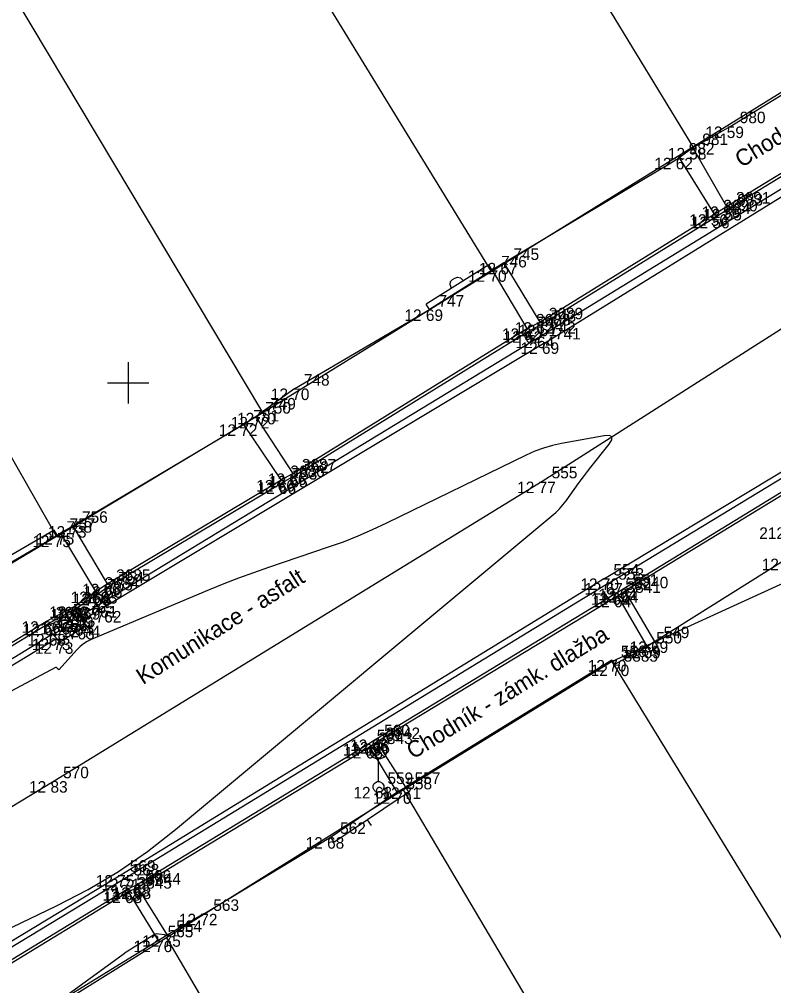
# Model space of a CAD drawing. Extents: x -703403 to -701924, y -1022520 to -1021856.
# Drawn here: x -703227.64 to -703209.32, y -1022139.64 to -1022116.18 of the extents above; entities that cross this region are included whole.
import ezdxf

# ---------------------------------------------------------------- set-up
doc = ezdxf.new("R2010")
doc.units = 0
for name, color, linetype in [('Ex_Minor Contours', 7, 'Continuous'), ('Z_bodove_pole_vysky', 7, 'Continuous'), ('Z_body', 7, 'Continuous'), ('Z_body_cisla', 7, 'Continuous'), ('Z_body_vysky_redukovane', 7, 'Continuous'), ('Z_budova', 7, 'Continuous'), ('Z_hektometricka_sit', 7, 'Continuous'), ('Z_katastr_hranice', 7, 'Continuous'), ('Z_katastr_vnitrni_kresba', 7, 'Continuous'), ('Z_komunikace', 7, 'Continuous'), ('Z_komunikace_osa', 7, 'Continuous'), ('Z_obruba', 7, 'Continuous'), ('Z_ploty', 7, 'Continuous'), ('Z_ploty_znacky', 7, 'Continuous'), ('Z_popisy', 7, 'Continuous'), ('Z_rozhranni', 7, 'Continuous'), ('Z_site_kanalizace_znaky', 7, 'Continuous'), ('Z_site_vo_znaky', 7, 'Continuous'), ('Z_vstupy', 7, 'Continuous'), ('Z_zlabek', 7, 'Continuous')]:
    doc.layers.add(name, color=color, linetype=linetype)

# ---------------------------------------------------------------- blocks, each defined once
blk = doc.blocks.new('POINT_DISPLAY')
blk.add_line((0, 0), (0, 0))
blk = doc.blocks.new('Z34')
for p, q in [((-0.2, 0.93), (-0.15, 1.02)), ((-0.15, 1.02), (-0.05, 1.07)), ((0.15, 0.72), (-0.15, 1.02)), ((0.15, 1.02), (-0.15, 0.72)), ((-0.05, 1.07), (0.05, 1.07)), ((0.05, 1.07), (0.15, 1.02)), ((0.15, 1.02), (0.2, 0.93)), ((-0.2, 0.82), (-0.2, 0.93)), ((-0.15, 0.72), (-0.2, 0.82)), ((-0.05, 0.68), (-0.15, 0.72)), ((0.15, 0.72), (0.05, 0.68)), ((0.2, 0.82), (0.15, 0.72)), ((0.2, 0.93), (0.2, 0.82)), ((0.05, 0.68), (-0.05, 0.68)), ((0, 0.13), (0, 0.68)), ((-0.13, 0.03), (-0.1, 0.08)), ((-0.13, -0.03), (-0.13, 0.03)), ((-0.1, 0.08), (-0.08, 0.1)), ((-0.08, 0.1), (-0.03, 0.13)), ((-0.03, 0.13), (0.03, 0.13)), ((0.03, 0.13), (0.08, 0.1)), ((0.08, 0.1), (0.1, 0.08)), ((0.1, 0.08), (0.13, 0.03)), ((0.13, 0.03), (0.13, -0.03)), ((-0.1, -0.08), (-0.13, -0.03)), ((-0.08, -0.1), (-0.1, -0.08)), ((-0.03, -0.13), (-0.08, -0.1)), ((0.03, -0.13), (-0.03, -0.13)), ((0.08, -0.1), (0.03, -0.13)), ((0.1, -0.08), (0.08, -0.1)), ((0.13, -0.03), (0.1, -0.08))]:
    blk.add_line(p, q)
blk = doc.blocks.new('Z46260')
for p, q in [((0.13, 0.13), (-0.13, 0.13)), ((-0.13, 0.13), (-0.13, -0.13)), ((0.13, 0), (-0.13, 0)), ((0.13, -0.13), (0.13, 0.13)), ((-0.13, -0.13), (0.13, -0.13))]:
    blk.add_line(p, q)
blk = doc.blocks.new('Z216')
for p, q in [((-0.17, 0), (-0.15, 0.1)), ((-0.15, 0.1), (-0.1, 0.15)), ((-0.1, 0.15), (-0.03, 0.17)), ((-0.03, 0.17), (0.03, 0.17)), ((0.03, 0.17), (0.1, 0.15)), ((0.1, 0.15), (0.15, 0.1)), ((0.15, 0.1), (0.17, 0))]:
    blk.add_line(p, q)
blk = doc.blocks.new('Z210')
blk.add_line((0, 0), (0, 0.17))

msp = doc.modelspace()

# ---------------------------------------------------------------- linework, layer by layer
at = {"layer": 'Ex_Minor Contours'}
for points in [[(-703231.075, -1022139.779), (-703226.738, -1022137.698), (-703225.974, -1022137.302), (-703225.237, -1022136.861), (-703224.53, -1022136.375), (-703223.851, -1022135.845), (-703214.703, -1022128.233), (-703214.609, -1022128.15), (-703214.52, -1022128.061), (-703214.438, -1022127.966), (-703214.361, -1022127.866), (-703214.065, -1022127.455), (-703213.991, -1022127.353), (-703213.915, -1022127.252), (-703213.838, -1022127.151), (-703213.76, -1022127.051), (-703213.316, -1022126.489), (-703213.248, -1022126.382), (-703213.245, -1022126.313), (-703213.307, -1022126.283), (-703213.434, -1022126.292), (-703214.469, -1022126.475), (-703214.692, -1022126.523), (-703214.91, -1022126.585), (-703215.123, -1022126.663), (-703215.332, -1022126.756), (-703218.722, -1022128.411), (-703219.069, -1022128.574), (-703219.421, -1022128.725), (-703219.778, -1022128.866), (-703220.139, -1022128.994), (-703221.593, -1022129.487), (-703221.955, -1022129.613), (-703222.315, -1022129.746), (-703222.673, -1022129.885), (-703223.028, -1022130.03), (-703225.895, -1022131.234), (-703225.993, -1022131.281), (-703226.084, -1022131.339), (-703226.168, -1022131.406), (-703226.245, -1022131.483), (-703226.673, -1022131.957), (-703226.68, -1022131.963), (-703226.688, -1022131.965), (-703226.695, -1022131.963), (-703226.702, -1022131.956), (-703226.73, -1022131.92), (-703226.737, -1022131.913), (-703226.746, -1022131.909), (-703226.754, -1022131.909), (-703226.764, -1022131.913), (-703230.733, -1022134.026)], [(-703226.72, -1022128.71), (-703226.64, -1022128.65)], [(-703224.05, -1022138.41), (-703224.316, -1022138.38), (-703224.32, -1022138.379), (-703224.324, -1022138.38), (-703224.327, -1022138.381), (-703224.331, -1022138.382), (-703224.348, -1022138.39), (-703224.354, -1022138.393), (-703224.358, -1022138.395), (-703224.817, -1022138.675), (-703224.894, -1022138.723), (-703224.97, -1022138.773), (-703225.045, -1022138.824), (-703225.119, -1022138.877), (-703226.755, -1022140.07)]]:
    msp.add_lwpolyline(points, dxfattribs=at)
at = {"layer": 'Z_budova'}
for p, q in [((-703211.28, -1022119.3), (-703211.61, -1022119.54)), ((-703215.87, -1022122.09), (-703211.61, -1022119.54)), ((-703216.16, -1022122.27), (-703216.24, -1022122.14)), ((-703215.87, -1022122.09), (-703216.16, -1022122.27)), ((-703221.9, -1022125.83), (-703222.19, -1022126.01)), ((-703221.77, -1022125.73), (-703221.9, -1022125.83)), ((-703222.19, -1022126.01), (-703226.34, -1022128.48)), ((-703226.34, -1022128.48), (-703226.64, -1022128.65)), ((-703226.72, -1022128.71), (-703226.8, -1022128.58)), ((-703226.64, -1022128.65), (-703226.72, -1022128.71)), ((-703213.25, -1022131.73), (-703218.26, -1022134.82)), ((-703213.25, -1022131.73), (-703213.18, -1022131.84)), ((-703218.26, -1022134.82), (-703218.18, -1022134.95)), ((-703224.26, -1022138.54), (-703229.25, -1022141.6)), ((-703224.05, -1022138.41), (-703224.26, -1022138.54))]:
    msp.add_line(p, q, dxfattribs=at)
at = {"layer": 'Z_hektometricka_sit'}
for p, q in [((-703225, -1022124.5), (-703225, -1022125.5)), ((-703225.5, -1022125), (-703224.5, -1022125))]:
    msp.add_line(p, q, dxfattribs=at)
at = {"layer": 'Z_katastr_hranice'}
for p, q in [((-703224.86, -1022108.15), (-703216.18, -1022122.3)), ((-703235.18, -1022113.95), (-703226.74, -1022128.73)), ((-703211.28, -1022119.27), (-703205.53, -1022115.72)), ((-703216.18, -1022122.3), (-703211.28, -1022119.27)), ((-703221.73, -1022125.72), (-703216.18, -1022122.3)), ((-703226.74, -1022128.73), (-703221.73, -1022125.72)), ((-703205.55, -1022128.24), (-703213.24, -1022131.77)), ((-703226.74, -1022128.73), (-703232.45, -1022132.14)), ((-703213.24, -1022131.77), (-703218.31, -1022134.88)), ((-703218.31, -1022134.88), (-703224.07, -1022138.47)), ((-703196.15, -1022172.3), (-703218.31, -1022134.88)), ((-703224.07, -1022138.47), (-703229.34, -1022141.75))]:
    msp.add_line(p, q, dxfattribs=at)
at = {"layer": 'Z_katastr_vnitrni_kresba'}
for p, q in [((-703221.49, -1022102.56), (-703211.28, -1022119.27)), ((-703221.73, -1022125.72), (-703231.79, -1022108.89)), ((-703190.45, -1022168.92), (-703213.24, -1022131.77)), ((-703224.07, -1022138.47), (-703208.36, -1022165.17))]:
    msp.add_line(p, q, dxfattribs=at)
at = {"layer": 'Z_komunikace'}
for p, q in [((-703214.86, -1022124.02), (-703204.83, -1022117.83)), ((-703214.86, -1022124.02), (-703226.12, -1022130.77)), ((-703213.43, -1022129.75), (-703207.78, -1022126.35)), ((-703213.43, -1022129.75), (-703225.18, -1022136.95)), ((-703226.12, -1022130.77), (-703226.01, -1022130.9)), ((-703226.01, -1022130.9), (-703226.66, -1022131.3)), ((-703226.73, -1022131.21), (-703231.61, -1022134.15)), ((-703226.66, -1022131.3), (-703226.73, -1022131.21)), ((-703225.18, -1022136.95), (-703231.78, -1022140.94))]:
    msp.add_line(p, q, dxfattribs=at)
at = {"layer": 'Z_komunikace_osa'}
for p, q in [((-703203.08, -1022119.83), (-703214.94, -1022127.4)), ((-703214.94, -1022127.4), (-703226.8, -1022134.67)), ((-703226.8, -1022134.67), (-703237.77, -1022141.31))]:
    msp.add_line(p, q, dxfattribs=at)
at = {"layer": 'Z_obruba'}
for p, q in [((-703210.46, -1022120.72), (-703205.08, -1022117.43)), ((-703204.92, -1022117.72), (-703214.98, -1022123.88)), ((-703210.76, -1022120.91), (-703210.46, -1022120.72)), ((-703215, -1022123.53), (-703210.76, -1022120.91)), ((-703215.31, -1022123.68), (-703215, -1022123.53)), ((-703221, -1022127.2), (-703215.31, -1022123.68)), ((-703214.98, -1022123.88), (-703226.17, -1022130.67)), ((-703213.31, -1022129.86), (-703207.72, -1022126.46)), ((-703207.53, -1022126.76), (-703212.93, -1022130.06)), ((-703221.28, -1022127.36), (-703221, -1022127.2)), ((-703225.51, -1022129.88), (-703221.28, -1022127.36)), ((-703225.79, -1022130.07), (-703225.51, -1022129.88)), ((-703213.31, -1022129.86), (-703225.09, -1022137.04)), ((-703226.31, -1022130.43), (-703225.79, -1022130.07)), ((-703213.11, -1022130.17), (-703212.93, -1022130.06)), ((-703218.97, -1022133.72), (-703213.11, -1022130.17)), ((-703226.98, -1022130.79), (-703226.31, -1022130.43)), ((-703231.74, -1022133.67), (-703226.98, -1022130.79)), ((-703226.84, -1022131.1), (-703231.66, -1022134.04)), ((-703224.77, -1022137.25), (-703219.14, -1022133.84)), ((-703219.14, -1022133.84), (-703218.97, -1022133.72)), ((-703225.09, -1022137.04), (-703231.7, -1022141.05)), ((-703229.96, -1022140.38), (-703224.99, -1022137.35)), ((-703224.99, -1022137.35), (-703224.77, -1022137.25))]:
    msp.add_line(p, q, dxfattribs=at)
at = {"layer": 'Z_ploty'}
for p, q in [((-703216.24, -1022122.14), (-703217.76, -1022123.09)), ((-703216.16, -1022122.27), (-703217.68, -1022123.22)), ((-703217.68, -1022123.22), (-703217.76, -1022123.09)), ((-703226.8, -1022128.58), (-703228.67, -1022129.67)), ((-703226.72, -1022128.71), (-703228.59, -1022129.8)), ((-703212.21, -1022131.28), (-703212.39, -1022131.41)), ((-703212.21, -1022131.28), (-703212.13, -1022131.41)), ((-703212.39, -1022131.41), (-703212.31, -1022131.53)), ((-703212.13, -1022131.41), (-703212.31, -1022131.53)), ((-703218.47, -1022134.94), (-703218.26, -1022134.82)), ((-703220.08, -1022136.03), (-703218.47, -1022134.94)), ((-703220, -1022136.15), (-703218.39, -1022135.07)), ((-703218.39, -1022135.07), (-703218.18, -1022134.95)), ((-703220.08, -1022136.03), (-703220, -1022136.15))]:
    msp.add_line(p, q, dxfattribs=at)
at = {"layer": 'Z_rozhranni'}
for p, q in [((-703226.17, -1022130.67), (-703226.28, -1022130.49)), ((-703226.84, -1022131.1), (-703226.95, -1022130.85)), ((-703226.17, -1022130.67), (-703226.12, -1022130.77)), ((-703226.84, -1022131.1), (-703226.73, -1022131.21))]:
    msp.add_line(p, q, dxfattribs=at)
at = {"layer": 'Z_vstupy'}
for p, q in [((-703210.37, -1022118.78), (-703207.13, -1022116.78)), ((-703211.28, -1022119.3), (-703210.37, -1022118.78)), ((-703220.95, -1022125.14), (-703217.68, -1022123.22)), ((-703220.95, -1022125.14), (-703221.77, -1022125.73)), ((-703212.21, -1022131.28), (-703209, -1022129.27)), ((-703212.39, -1022131.41), (-703213.18, -1022131.84)), ((-703223.16, -1022137.89), (-703220.08, -1022136.03)), ((-703223.16, -1022137.89), (-703224.05, -1022138.41))]:
    msp.add_line(p, q, dxfattribs=at)
at = {"layer": 'Z_zlabek'}
for p, q in [((-703210.42, -1022120.78), (-703205.05, -1022117.49)), ((-703211.28, -1022119.3), (-703210.46, -1022120.72)), ((-703211.61, -1022119.54), (-703210.76, -1022120.91)), ((-703210.72, -1022120.97), (-703210.42, -1022120.78)), ((-703214.96, -1022123.59), (-703210.72, -1022120.97)), ((-703215.87, -1022122.09), (-703215, -1022123.53)), ((-703216.16, -1022122.27), (-703215.31, -1022123.68)), ((-703215.27, -1022123.75), (-703214.96, -1022123.59)), ((-703220.97, -1022127.26), (-703215.27, -1022123.75)), ((-703221.9, -1022125.83), (-703221, -1022127.2)), ((-703221.28, -1022127.36), (-703222.19, -1022126.01)), ((-703212.97, -1022130), (-703207.57, -1022126.7)), ((-703221.25, -1022127.42), (-703220.97, -1022127.26)), ((-703225.47, -1022129.94), (-703221.25, -1022127.42)), ((-703226.34, -1022128.48), (-703225.51, -1022129.88)), ((-703226.64, -1022128.65), (-703225.79, -1022130.07)), ((-703226.28, -1022130.49), (-703225.74, -1022130.12)), ((-703225.74, -1022130.12), (-703225.47, -1022129.94)), ((-703219, -1022133.66), (-703213.15, -1022130.11)), ((-703213.15, -1022130.11), (-703212.97, -1022130)), ((-703212.93, -1022130.06), (-703212.21, -1022131.28)), ((-703213.11, -1022130.17), (-703212.39, -1022131.41)), ((-703226.95, -1022130.85), (-703226.28, -1022130.49)), ((-703231.7, -1022133.73), (-703226.95, -1022130.85)), ((-703219.18, -1022133.77), (-703219, -1022133.66)), ((-703224.8, -1022137.19), (-703219.18, -1022133.77)), ((-703219.14, -1022133.84), (-703218.47, -1022134.94)), ((-703218.97, -1022133.72), (-703218.26, -1022134.82)), ((-703225.02, -1022137.29), (-703224.8, -1022137.19)), ((-703230, -1022140.32), (-703225.02, -1022137.29)), ((-703224.26, -1022138.54), (-703224.99, -1022137.35)), ((-703224.77, -1022137.25), (-703224.05, -1022138.41))]:
    msp.add_line(p, q, dxfattribs=at)

# ---------------------------------------------------------------- block references
at = {"layer": 'Z_body'}
for p in [(-703210.37, -1022118.78), (-703211.28, -1022119.3), (-703211.61, -1022119.54), (-703210.46, -1022120.72), (-703210.42, -1022120.78), (-703210.76, -1022120.91), (-703210.72, -1022120.97), (-703215.87, -1022122.09), (-703216.16, -1022122.27), (-703217.68, -1022123.22), (-703215, -1022123.53), (-703214.96, -1022123.59), (-703215.31, -1022123.68), (-703215.27, -1022123.75), (-703214.98, -1022123.88), (-703214.86, -1022124.02), (-703220.95, -1022125.14), (-703221.9, -1022125.83), (-703221.77, -1022125.73), (-703222.19, -1022126.01), (-703221, -1022127.2), (-703220.97, -1022127.26), (-703221.28, -1022127.36), (-703221.25, -1022127.42), (-703214.94, -1022127.4), (-703226.34, -1022128.48), (-703226.72, -1022128.71), (-703226.64, -1022128.65), (-703225.51, -1022129.88), (-703213.43, -1022129.75), (-703213.31, -1022129.86), (-703225.79, -1022130.07), (-703225.74, -1022130.12), (-703225.47, -1022129.94), (-703213.15, -1022130.11), (-703212.97, -1022130), (-703212.93, -1022130.06), (-703213.11, -1022130.17), (-703226.31, -1022130.43), (-703226.28, -1022130.49), (-703226.98, -1022130.79), (-703226.95, -1022130.85), (-703226.53, -1022130.83), (-703226.17, -1022130.67), (-703226.12, -1022130.77), (-703226.84, -1022131.1), (-703226.01, -1022130.9), (-703226.73, -1022131.21), (-703226.66, -1022131.3), (-703212.21, -1022131.28), (-703212.39, -1022131.41), (-703213.25, -1022131.73), (-703213.18, -1022131.84), (-703219, -1022133.66), (-703219.18, -1022133.77), (-703219.14, -1022133.84), (-703218.97, -1022133.72), (-703226.8, -1022134.67), (-703218.92, -1022134.81), (-703218.26, -1022134.82), (-703218.47, -1022134.94), (-703220.08, -1022136.03), (-703225.18, -1022136.95), (-703225.09, -1022137.04), (-703224.8, -1022137.19), (-703225.02, -1022137.29), (-703224.99, -1022137.35), (-703224.77, -1022137.25), (-703223.16, -1022137.89), (-703224.26, -1022138.54), (-703224.05, -1022138.41)]:
    msp.add_blockref('POINT_DISPLAY', p, dxfattribs=at)
at = {"layer": 'Z_ploty_znacky'}
for name, p, rotation in [('Z216', (-703217, -1022122.62), 32.2), ('Z210', (-703212.22, -1022131.47), -144.70000000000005), ('Z210', (-703219.19, -1022135.61), -146.00000000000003)]:
    msp.add_blockref(name, p, dxfattribs=dict(at, rotation=rotation))
at = {"layer": 'Z_site_kanalizace_znaky', "rotation": 29.699999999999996}
msp.add_blockref('Z46260', (-703226.53, -1022130.83), dxfattribs=at)
at = {"layer": 'Z_site_vo_znaky'}
msp.add_blockref('Z34', (-703218.92, -1022134.81), dxfattribs=at)

# ---------------------------------------------------------------- texts
at = {"layer": 'Z_bodove_pole_vysky'}
msp.add_text('212,64', height=0.28, dxfattribs=at).set_placement((-703209.667, -1022128.79))
at = {"layer": 'Z_body_cisla'}
for s, p in [('980', (-703210.14, -1022118.7)), ('981', (-703211.05, -1022119.23)), ('982', (-703211.38, -1022119.46)), ('3691', (-703210.23, -1022120.65)), ('983', (-703210.2, -1022120.7)), ('3690', (-703210.54, -1022120.84)), ('984', (-703210.5, -1022120.9)), ('746', (-703215.94, -1022122.2)), ('745', (-703215.64, -1022122.02)), ('747', (-703217.46, -1022123.15)), ('3688', (-703215.09, -1022123.61)), ('3689', (-703214.78, -1022123.46)), ('743', (-703214.74, -1022123.52)), ('744', (-703215.05, -1022123.68)), ('742', (-703214.75, -1022123.81)), ('741', (-703214.63, -1022123.95)), ('748', (-703220.73, -1022125.07)), ('750', (-703221.67, -1022125.75)), ('749', (-703221.55, -1022125.65)), ('751', (-703221.96, -1022125.94)), ('3687', (-703220.78, -1022127.13)), ('3686', (-703221.06, -1022127.29)), ('753', (-703221.03, -1022127.35)), ('752', (-703220.75, -1022127.19)), ('555', (-703214.71, -1022127.32)), ('756', (-703226.12, -1022128.4)), ('758', (-703226.5, -1022128.64)), ('757', (-703226.42, -1022128.57)), ('554', (-703213.21, -1022129.68)), ('3685', (-703225.29, -1022129.81)), ('754', (-703225.24, -1022129.87)), ('553', (-703213.09, -1022129.78)), ('551', (-703212.74, -1022129.93)), ('3684', (-703225.57, -1022130)), ('755', (-703225.51, -1022130.04)), ('552', (-703212.92, -1022130.03)), ('3841', (-703212.89, -1022130.1)), ('3840', (-703212.71, -1022129.99)), ('3683', (-703226.09, -1022130.36)), ('759', (-703226.05, -1022130.41)), ('765', (-703225.95, -1022130.6)), ('3682', (-703226.76, -1022130.72)), ('760', (-703226.72, -1022130.78)), ('769', (-703226.3, -1022130.75)), ('761', (-703225.89, -1022130.7)), ('762', (-703225.79, -1022130.82)), ('766', (-703226.62, -1022131.03)), ('764', (-703226.5, -1022131.14)), ('763', (-703226.44, -1022131.23)), ('550', (-703212.17, -1022131.33)), ('549', (-703211.99, -1022131.2)), ('556', (-703213.03, -1022131.66)), ('3885', (-703212.96, -1022131.77)), ('561', (-703218.96, -1022133.7)), ('560', (-703218.78, -1022133.58)), ('3842', (-703218.74, -1022133.65)), ('3843', (-703218.92, -1022133.77)), ('570', (-703226.58, -1022134.6)), ('559', (-703218.7, -1022134.74)), ('558', (-703218.24, -1022134.87)), ('557', (-703218.04, -1022134.74)), ('562', (-703219.85, -1022135.95)), ('569', (-703224.96, -1022136.87)), ('568', (-703224.87, -1022136.96)), ('567', (-703224.8, -1022137.21)), ('566', (-703224.58, -1022137.11)), ('3844', (-703224.55, -1022137.18)), ('3845', (-703224.77, -1022137.28)), ('563', (-703222.93, -1022137.82)), ('564', (-703223.83, -1022138.33)), ('565', (-703224.04, -1022138.46))]:
    msp.add_text(s, height=0.28, dxfattribs=at).set_placement(p)
at = {"layer": 'Z_body_vysky_redukovane'}
for s, p in [('12 59', (-703210.977, -1022119.06)), ('12 58', (-703211.887, -1022119.58)), ('12 62', (-703212.217, -1022119.82)), ('12 56', (-703211.067, -1022121)), ('12 55', (-703211.027, -1022121.06)), ('12 56', (-703211.367, -1022121.19)), ('12 56', (-703211.327, -1022121.25)), ('12 67', (-703216.477, -1022122.37)), ('12 70', (-703216.743, -1022122.55)), ('12 69', (-703218.287, -1022123.5)), ('12 62', (-703215.607, -1022123.81)), ('12 61', (-703215.52, -1022123.87)), ('12 62', (-703215.917, -1022123.96)), ('12 62', (-703215.877, -1022124.03)), ('12 64', (-703215.587, -1022124.16)), ('12 69', (-703215.467, -1022124.3)), ('12 70', (-703221.533, -1022125.42)), ('12 72', (-703222.507, -1022126.11)), ('12 70', (-703222.353, -1022126.01)), ('12 72', (-703222.797, -1022126.29)), ('12 66', (-703221.607, -1022127.48)), ('12 65', (-703221.577, -1022127.54)), ('12 66', (-703221.887, -1022127.64)), ('12 66', (-703221.857, -1022127.7)), ('12 77', (-703215.547, -1022127.68)), ('12 73', (-703226.947, -1022128.76)), ('12 75', (-703227.327, -1022128.99)), ('12 75', (-703227.247, -1022128.93)), ('12 66', (-703209.607, -1022129.55)), ('12 66', (-703226.117, -1022130.16)), ('12 70', (-703214.013, -1022130.03)), ('12 67', (-703213.917, -1022130.14)), ('12 66', (-703226.397, -1022130.35)), ('12 66', (-703226.347, -1022130.4)), ('12 66', (-703226.077, -1022130.22)), ('12 64', (-703213.757, -1022130.39)), ('12 64', (-703213.577, -1022130.28)), ('12 64', (-703213.537, -1022130.34)), ('12 64', (-703213.717, -1022130.45)), ('12 66', (-703226.917, -1022130.71)), ('12 66', (-703226.887, -1022130.77)), ('12 66', (-703227.587, -1022131.07)), ('12 66', (-703227.557, -1022131.13)), ('12 67', (-703227.137, -1022131.11)), ('12 69', (-703226.777, -1022130.95)), ('12 72', (-703226.727, -1022131.05)), ('12 68', (-703227.447, -1022131.38)), ('12 74', (-703226.617, -1022131.18)), ('12 73', (-703227.337, -1022131.49)), ('12 73', (-703227.267, -1022131.58)), ('12 69', (-703212.817, -1022131.56)), ('12 69', (-703212.997, -1022131.69)), ('12 70', (-703213.833, -1022132.01)), ('12 70', (-703213.763, -1022132.12)), ('12 66', (-703219.607, -1022133.94)), ('12 65', (-703219.787, -1022134.05)), ('12 66', (-703219.747, -1022134.12)), ('12 66', (-703219.577, -1022134)), ('12 83', (-703227.407, -1022134.95)), ('12 68', (-703219.527, -1022135.09)), ('12 71', (-703218.82, -1022135.1)), ('12 70', (-703219.053, -1022135.22)), ('12 68', (-703220.687, -1022136.31)), ('12 75', (-703225.787, -1022137.23)), ('12 71', (-703225.65, -1022137.32)), ('12 68', (-703225.407, -1022137.47)), ('12 68', (-703225.627, -1022137.57)), ('12 68', (-703225.597, -1022137.63)), ('12 68', (-703225.377, -1022137.53)), ('12 72', (-703223.767, -1022138.17)), ('12 76', (-703224.867, -1022138.82)), ('12 75', (-703224.657, -1022138.69))]:
    msp.add_text(s, height=0.28, dxfattribs=at).set_placement(p)
at = {"layer": 'Z_popisy'}
for s, rotation, p in [('Chodník - zámk. dlažba', 31.5, (-703210.1, -1022119.79)), ('Komunikace - asfalt', 32.4, (-703224.64, -1022132.34)), ('Chodník - zámk. dlažba', 31.5, (-703218.08, -1022134.15))]:
    msp.add_text(s, height=0.4, rotation=rotation, dxfattribs=at).set_placement(p)

doc.saveas('drawing.dxf')
